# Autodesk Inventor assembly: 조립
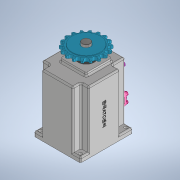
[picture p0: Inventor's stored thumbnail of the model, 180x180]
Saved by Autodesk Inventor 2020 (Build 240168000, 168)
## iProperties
Created: 2022-01
Part Number: 조립
Document SubType Name: Assembly
Designer: user
Author: user
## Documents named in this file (16)
- C:\Users\user\Desktop\720112V1015\조립.iam
- C:\Users\user\Desktop\720112V1015\멈춤나사 M3.ipt
- C:\Users\user\Desktop\720112V1015\메인 축.ipt
- C:\Users\user\Desktop\720112V1015\베어링 608.ipt
- C:\Users\user\Desktop\720112V1015\베어링 6003.ipt
- C:\Users\user\Desktop\720112V1015\본체.ipt
- C:\Users\user\Desktop\720112V1015\볼트 M4 x 10.ipt
- C:\Users\user\Desktop\720112V1015\부시.ipt
- C:\Users\user\Desktop\720112V1015\상부 캡.ipt
- C:\Users\user\Desktop\720112V1015\서브 축.ipt
- C:\Users\user\Desktop\720112V1015\스프로킷.ipt
- C:\Users\user\Desktop\720112V1015\슬라이더.ipt
- C:\Users\user\Desktop\720112V1015\오일 실 8 x 22 x 7.ipt
- C:\Users\user\Desktop\720112V1015\오일 실 17 x 32 x 8.ipt
- C:\Users\user\Desktop\720112V1015\커버.ipt
- C:\Users\user\Desktop\720112V1015\키 5 x 5.ipt
